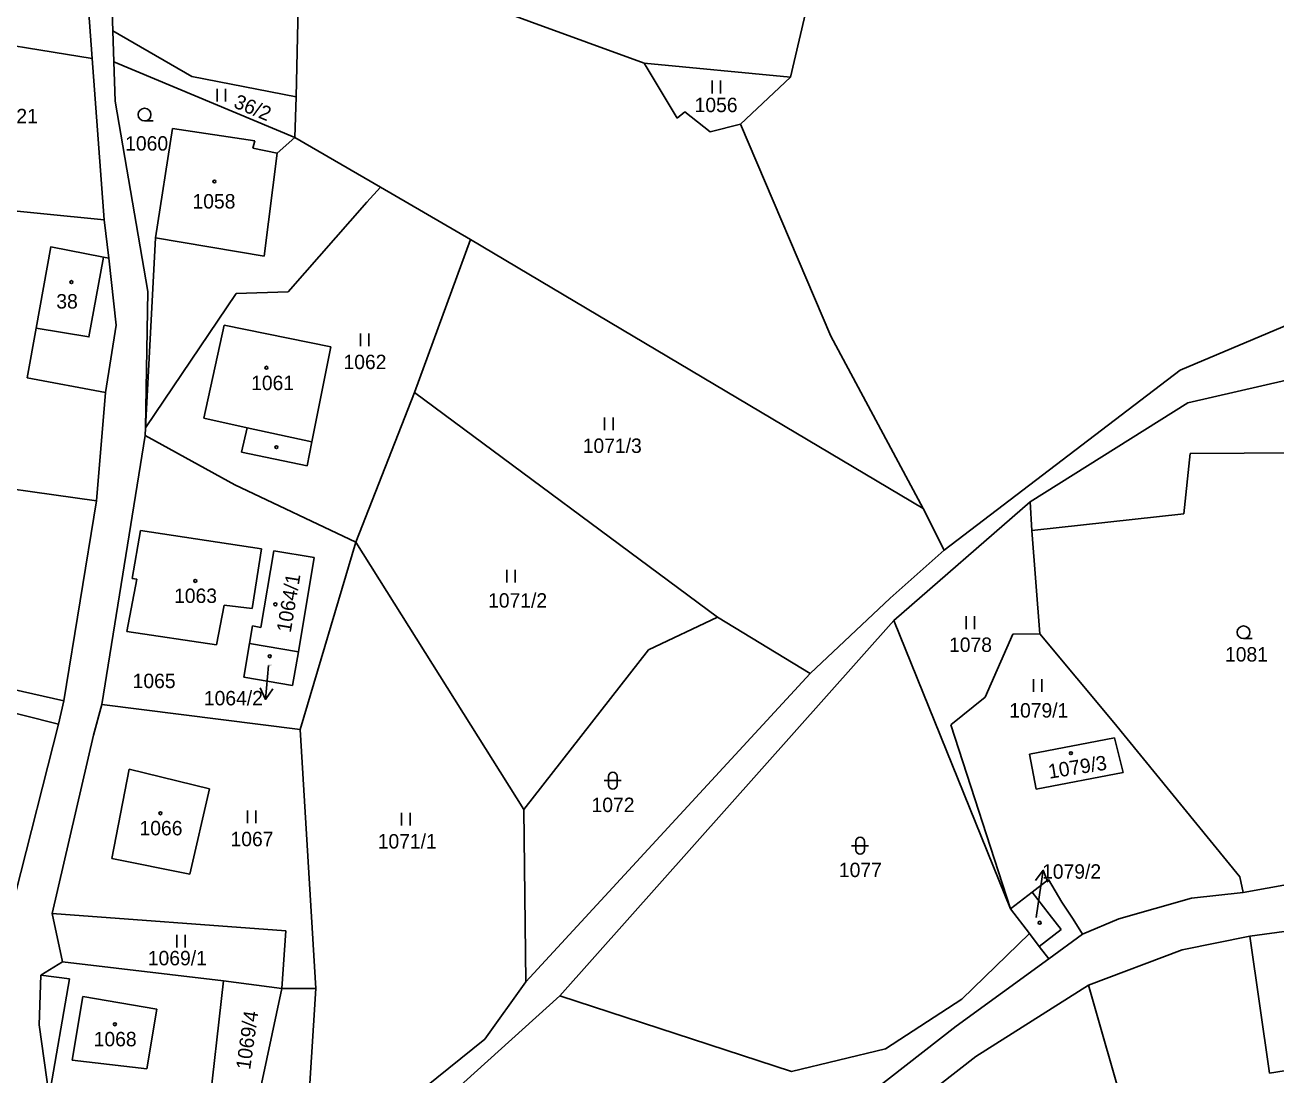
# Model space of a CAD drawing. Extents: x -670359 to -668019, y -978807 to -976674.
# Drawn here: x -670130.3 to -669982.9, y -977711.4 to -977587.7 of the extents above; entities that cross this region are included whole.
import ezdxf

# ---------------------------------------------------------------- set-up
doc = ezdxf.new("R2010")
doc.units = 0
for name, color, linetype in [('Hranice parcel', 7, 'Continuous'), ('Parcelní čísla', 7, 'Continuous'), ('Vnitřní kresba', 7, 'Continuous'), ('Značky budov', 7, 'Continuous'), ('Značky kultur', 7, 'Continuous')]:
    doc.layers.add(name, color=color, linetype=linetype)

msp = doc.modelspace()

# ---------------------------------------------------------------- linework, layer by layer
at = {"layer": 'Hranice parcel'}
msp.add_line((-670106.89, -977700.29), (-670100, -977701.17), dxfattribs=at)
for points in [[(-670125.26, -977552.07), (-670122.35, -977591.65)], [(-670033.24, -977564.47), (-670040.09, -977593.86)], [(-670120.58, -977569.54), (-670119.93, -977588.41)], [(-670098.33, -977596.16), (-670097.83, -977573.12)], [(-670057.34, -977592.2), (-670077.72, -977584.8)], [(-670098.33, -977596.16), (-670110.6, -977593.79), (-670119.93, -977588.41)], [(-670119.93, -977588.41), (-670119.81, -977592.06)], [(-670139.34, -977588.92), (-670122.35, -977591.65)], [(-670120.96, -977610.65), (-670122.35, -977591.65)], [(-670119.65, -977596.66), (-670119.81, -977592.06)], [(-670119.81, -977592.06), (-670098.48, -977600.97)], [(-670040.09, -977593.86), (-670057.34, -977592.2)], [(-670053.45, -977598.69), (-670057.34, -977592.2)], [(-670040.09, -977593.86), (-670045.97, -977599.39)], [(-670115.81, -977619.08), (-670119.65, -977596.66)], [(-670098.48, -977600.97), (-670098.33, -977596.16)], [(-670052.56, -977597.95), (-670053.45, -977598.69)], [(-670049.57, -977600.29), (-670052.56, -977597.95)], [(-670114.89, -977612.77), (-670112.88, -977599.91)], [(-670112.88, -977599.91), (-670103.2, -977601.34)], [(-670045.97, -977599.39), (-670049.57, -977600.29)], [(-670045.97, -977599.39), (-670035.35, -977624.36)], [(-670103.2, -977601.34), (-670103.45, -977602.21)], [(-670100.57, -977602.79), (-670098.48, -977600.97)], [(-670098.48, -977600.97), (-670088.41, -977606.81)], [(-670103.45, -977602.21), (-670100.57, -977602.79)], [(-670089.99, -977608.59), (-670088.41, -977606.81)], [(-670077.79, -977612.97), (-670088.41, -977606.81)], [(-670135.99, -977609.18), (-670120.96, -977610.65)], [(-670099.27, -977619.12), (-670089.99, -977608.59)], [(-670120.96, -977610.65), (-670120.4, -977615.18)], [(-670116.08, -977635.17), (-670114.89, -977612.77)], [(-670077.79, -977612.97), (-670084.4, -977630.98)], [(-670024.45, -977644.67), (-670077.79, -977612.97)], [(-670128.95, -977623.4), (-670127.24, -977613.84), (-670121.02, -977615.06)], [(-670121.02, -977615.06), (-670120.4, -977615.18)], [(-670120.4, -977615.18), (-670119.52, -977623.06)], [(-669964.98, -977616.04), (-669994.19, -977628.36)], [(-670115.81, -977619.08), (-670116.08, -977635.17)], [(-670116.08, -977635.17), (-670105.41, -977619.32)], [(-670105.41, -977619.32), (-670099.27, -977619.12)], [(-670130, -977629.28), (-670128.95, -977623.4)], [(-670119.52, -977623.06), (-670120.78, -977631)], [(-670106.8, -977623.06), (-670109.2, -977634)], [(-670106.8, -977623.06), (-670094.25, -977625.63)], [(-670035.35, -977624.36), (-670024.45, -977644.67)], [(-670094.25, -977625.63), (-670096.5, -977636.81)], [(-669993.29, -977632.19), (-669970.04, -977626.86)], [(-669994.19, -977628.36), (-670022.01, -977649.57)], [(-670130, -977629.28), (-670120.78, -977631)], [(-670120.78, -977631), (-670121.83, -977643.75)], [(-670084.4, -977630.98), (-670091.3, -977648.61)], [(-670084.4, -977630.98), (-670048.71, -977657.46)], [(-670011.88, -977643.88), (-669993.29, -977632.19)], [(-670109.2, -977634), (-670104.09, -977635.16)], [(-670116.1, -977636.04), (-670116.08, -977635.17)], [(-670104.09, -977635.16), (-670104.75, -977638.03)], [(-670121.21, -977667.75), (-670116.1, -977636.04)], [(-670105.57, -977641.87), (-670114.88, -977636.72), (-670116.1, -977636.04)], [(-670096.5, -977636.81), (-670097.05, -977639.62)], [(-670097.05, -977639.62), (-670104.75, -977638.03)], [(-670139.74, -977641.23), (-670121.83, -977643.75)], [(-670091.3, -977648.61), (-670105.57, -977641.87)], [(-670121.83, -977643.75), (-670125.68, -977667.32)], [(-670027.91, -977657.85), (-670011.88, -977643.88)], [(-670022.01, -977649.57), (-670024.45, -977644.67)], [(-670011.88, -977643.88), (-670011.67, -977647.24)], [(-670117.66, -977652.9), (-670116.66, -977647.23)], [(-670116.66, -977647.23), (-670102.43, -977649.41)], [(-670011.67, -977647.24), (-670010.71, -977659.41)], [(-670091.3, -977648.61), (-670097.86, -977670.7)], [(-670091.3, -977648.61), (-670071.52, -977680.1)], [(-670102.43, -977649.41), (-670103.52, -977656.44)], [(-670102.48, -977658.66), (-670100.94, -977649.63)], [(-670100.94, -977649.63), (-670096.19, -977650.44)], [(-670096.19, -977650.44), (-670098.07, -977661.52)], [(-670022.01, -977649.57), (-670028.37, -977655.2)], [(-670118.26, -977659.13), (-670117.1, -977652.98)], [(-670117.1, -977652.98), (-670117.66, -977652.9)], [(-670106.8, -977656.02), (-670107.71, -977660.73)], [(-670103.52, -977656.44), (-670106.8, -977656.02)], [(-670028.37, -977655.2), (-670037.79, -977664.1)], [(-670067.28, -977702.04), (-670027.91, -977657.85)], [(-670056.82, -977661.32), (-670048.71, -977657.46)], [(-670048.71, -977657.46), (-670037.79, -977664.1)], [(-670027.91, -977657.85), (-670014.19, -977691.82)], [(-670107.71, -977660.73), (-670118.26, -977659.13)], [(-670103.82, -977660.54), (-670103.47, -977658.49)], [(-670103.47, -977658.49), (-670102.48, -977658.66)], [(-670010.71, -977659.41), (-670013.91, -977659.46)], [(-670010.71, -977659.41), (-670001.99, -977669.86)], [(-670104.5, -977664.53), (-670103.82, -977660.54)], [(-670103.82, -977660.54), (-670098.07, -977661.52)], [(-670013.91, -977659.46), (-670017.17, -977666.88)], [(-670098.07, -977661.52), (-670098.75, -977665.51)], [(-670071.52, -977680.1), (-670056.82, -977661.32)], [(-670143.98, -977663.19), (-670125.68, -977667.32)], [(-670098.75, -977665.51), (-670104.5, -977664.53)], [(-670037.79, -977664.1), (-670071.26, -977700.41)], [(-670125.68, -977667.32), (-670126.34, -977670.04)], [(-670122.19, -977671.34), (-670121.21, -977667.75)], [(-670097.86, -977670.7), (-670121.21, -977667.75)], [(-670017.17, -977666.88), (-670021.19, -977670.13)], [(-670126.34, -977670.04), (-670131.37, -977689.99)], [(-670097.86, -977670.7), (-670096, -977701.2)], [(-670021.19, -977670.13), (-670014.19, -977691.82)], [(-670001.99, -977669.86), (-669987.15, -977688.04)], [(-670127.06, -977692.34), (-670122.19, -977671.34)], [(-670001.92, -977671.66), (-670011.93, -977673.59)], [(-670000.91, -977675.76), (-670001.92, -977671.66)], [(-670011.93, -977673.59), (-670011.14, -977677.72)], [(-670120.05, -977685.88), (-670117.98, -977675.37)], [(-670117.98, -977675.37), (-670108.55, -977677.68)], [(-670011.14, -977677.72), (-670000.91, -977675.76)], [(-670108.55, -977677.68), (-670110.87, -977687.74)], [(-670071.26, -977700.41), (-670071.52, -977680.1)], [(-670110.87, -977687.74), (-670120.05, -977685.88)], [(-669957.62, -977684.64), (-669986.76, -977689.88)], [(-670011.62, -977689.84), (-670009.72, -977688.37)], [(-670009.72, -977688.37), (-670008.14, -977691.01)], [(-669987.15, -977688.04), (-669986.76, -977689.88)], [(-670011.62, -977689.84), (-670014.19, -977691.82)], [(-669986.76, -977689.88), (-669992.85, -977690.56)], [(-670014.19, -977691.82), (-670011.96, -977694.72)], [(-670008.14, -977691.01), (-670006.79, -977693.02)], [(-669992.85, -977690.56), (-670001.43, -977692.98)], [(-670125.86, -977698.04), (-670127.06, -977692.34)], [(-670099.55, -977694.38), (-670127.06, -977692.34)], [(-670006.79, -977693.02), (-670005.69, -977694.79)], [(-670001.43, -977692.98), (-670005.69, -977694.79)], [(-669972.97, -977693.24), (-669985.99, -977695.04)], [(-670100, -977701.17), (-670099.55, -977694.38)], [(-670019.9, -977702.45), (-670011.96, -977694.72)], [(-670011.96, -977694.72), (-670010.79, -977696.24)], [(-670005.69, -977694.79), (-670009.67, -977697.69)], [(-670010.79, -977696.24), (-670009.67, -977697.69)], [(-669985.99, -977695.04), (-669993.94, -977696.63)], [(-669985.99, -977695.04), (-669983.66, -977711.17)], [(-670020.57, -977705.64), (-670009.67, -977697.69)], [(-669993.94, -977696.63), (-670005.01, -977700.79)], [(-670128.4, -977699.61), (-670125.86, -977698.04)], [(-670125.86, -977698.04), (-670106.89, -977700.29)], [(-670128.6, -977705.45), (-670128.4, -977699.61)], [(-670106.89, -977700.29), (-670108.73, -977716.63)], [(-670071.26, -977700.41), (-670076.09, -977707.16)], [(-670124.71, -977709.64), (-670123.45, -977702.13)], [(-670123.45, -977702.13), (-670114.74, -977703.63)], [(-670100, -977701.17), (-670104.16, -977720.69)], [(-670096, -977701.2), (-670100, -977701.17)], [(-670096, -977701.2), (-670097.32, -977721.73)], [(-670097.16, -977729.02), (-670067.28, -977702.04)], [(-670067.28, -977702.04), (-670039.97, -977710.95)], [(-670005.01, -977700.79), (-670018.27, -977709.18)], [(-670005.01, -977700.79), (-669996.13, -977731.83)], [(-670114.74, -977703.63), (-670115.91, -977710.66)], [(-670028.91, -977708.31), (-670019.9, -977702.45)], [(-670128.6, -977705.45), (-670127.44, -977713.87)], [(-670020.57, -977705.64), (-670038.59, -977719.67)], [(-670076.09, -977707.16), (-670097.12, -977724.06)], [(-670039.97, -977710.95), (-670028.91, -977708.31)], [(-670018.27, -977709.18), (-670035.74, -977722.81)], [(-669983.66, -977711.17), (-669966.96, -977708.51)], [(-670115.91, -977710.66), (-670124.71, -977709.64)]]:
    msp.add_lwpolyline(points, dxfattribs=at)
at = {"layer": 'Parcelní čísla'}
for p, q in [((-670101.06, -977665.9), (-670101.92, -977667.14)), ((-670011.25, -977688.45), (-670010.32, -977687.27)), ((-670011.15, -977692.81), (-670010.91, -977691.23))]:
    msp.add_line(p, q, dxfattribs=at)
for points in [[(-670101.57, -977663.15), (-670101.92, -977667.14), (-670102.55, -977665.78)], [(-670010.91, -977691.23), (-670010.32, -977687.27), (-670009.77, -977688.67)]]:
    msp.add_lwpolyline(points, dxfattribs=at)
at = {"layer": 'Vnitřní kresba'}
for points in [[(-670100.57, -977602.79), (-670102.1, -977614.94)], [(-670102.1, -977614.94), (-670114.89, -977612.77)], [(-670121.02, -977615.06), (-670122.74, -977624.45), (-670128.95, -977623.4)], [(-670104.09, -977635.16), (-670096.5, -977636.81)], [(-669993.77, -977645.3), (-669993.01, -977638.18)], [(-669993.01, -977638.18), (-669967.58, -977638.03)], [(-670011.67, -977647.24), (-669993.77, -977645.3)], [(-670138.8, -977666.91), (-670126.34, -977670.04)], [(-670009.61, -977692.44), (-670011.62, -977689.84)], [(-670008.21, -977694.24), (-670009.61, -977692.44)], [(-670010.79, -977696.24), (-670008.21, -977694.24)], [(-670128.4, -977699.61), (-670125.04, -977700.04)], [(-670125.04, -977700.04), (-670127.44, -977713.87)]]:
    msp.add_lwpolyline(points, dxfattribs=at)
at = {"layer": 'Značky budov'}
for centre in [(-670107.96, -977606.14), (-670124.8, -977617.99), (-670101.83, -977628.08), (-670110.21, -977653.18), (-670100.78, -977655.94), (-670101.44, -977662.05), (-670007.07, -977673.47), (-670114.32, -977680.55), (-670010.74, -977693.45), (-670119.68, -977705.4)]:
    msp.add_circle(centre, 0.175, dxfattribs=at)
at = {"layer": 'Značky kultur'}
for p, q in [((-670049.33, -977594.26), (-670049.33, -977595.76)), ((-670048.33, -977595.76), (-670048.33, -977594.26)), ((-670107.64, -977595.21), (-670107.64, -977596.71)), ((-670106.64, -977596.71), (-670106.64, -977595.21)), ((-670116.19, -977599.01), (-670115.19, -977599.01)), ((-670090.75, -977624.04), (-670090.75, -977625.54)), ((-670089.75, -977625.54), (-670089.75, -977624.04)), ((-670062, -977633.92), (-670062, -977635.42)), ((-670061, -977635.42), (-670061, -977633.92)), ((-670073.52, -977651.88), (-670073.52, -977653.38)), ((-670072.52, -977653.38), (-670072.52, -977651.88)), ((-670019.42, -977657.35), (-670019.42, -977658.85)), ((-670018.42, -977658.85), (-670018.42, -977657.35)), ((-669986.73, -977659.98), (-669985.73, -977659.98)), ((-670011.47, -977664.76), (-670011.47, -977666.26)), ((-670010.47, -977666.26), (-670010.47, -977664.76)), ((-670062.03, -977676.71), (-670060.03, -977676.71)), ((-670061.53, -977676.21), (-670061.53, -977677.21)), ((-670060.53, -977676.21), (-670060.53, -977677.21)), ((-670104.06, -977680.23), (-670104.06, -977681.73)), ((-670103.06, -977681.73), (-670103.06, -977680.23)), ((-670085.91, -977680.51), (-670085.91, -977682.01)), ((-670084.91, -977682.01), (-670084.91, -977680.51)), ((-670032.89, -977684.37), (-670030.89, -977684.37)), ((-670032.39, -977683.87), (-670032.39, -977684.87)), ((-670031.39, -977683.87), (-670031.39, -977684.87)), ((-670112.39, -977694.86), (-670112.39, -977696.36)), ((-670111.39, -977696.36), (-670111.39, -977694.86))]:
    msp.add_line(p, q, dxfattribs=at)
for centre, radius in [((-670116.19, -977598.26), 0.75), ((-670107.96, -977606.14), 0.175), ((-670124.8, -977617.99), 0.175), ((-670101.83, -977628.08), 0.175), ((-670100.65, -977637.43), 0.175), ((-670110.21, -977653.18), 0.175), ((-670100.78, -977655.94), 0.175), ((-669986.73, -977659.23), 0.75), ((-670101.44, -977662.05), 0.175), ((-670007.07, -977673.47), 0.175), ((-670114.32, -977680.55), 0.175), ((-670010.74, -977693.45), 0.175), ((-670119.68, -977705.4), 0.175)]:
    msp.add_circle(centre, radius, dxfattribs=at)
for centre, start, end in [((-670061.03, -977676.21), 0, 180), ((-670061.03, -977677.21), 180, 0), ((-670031.89, -977683.87), 0, 180), ((-670031.89, -977684.87), 180, 0)]:
    msp.add_arc(centre, 0.5, start, end, dxfattribs=at)

# ---------------------------------------------------------------- texts
at = {"layer": 'Parcelní čísla'}
for s, rotation, p in [('36/2', 337.4827, (-670105.81, -977597.37)), ('1064/1', 80.3948, (-670098.97, -977659.34)), ('1079/3', 9.0395, (-670009.6, -977676.49)), ('1069/4', 81.9, (-670103.75, -977710.83))]:
    msp.add_text(s, height=1.7, rotation=rotation, dxfattribs=at).set_placement(p)
for s, height, p in [('27/21', 1.7, (-670134.45, -977599.28)), ('1056', 1.7, (-670051.39, -977597.97)), ('1060', 1.7, (-670118.47, -977602.5)), ('1058', 1.7, (-670110.54, -977609.32)), ('38', 1.7, (-670126.58, -977621.1)), ('1062', 1.7, (-670092.75, -977628.24)), ('1061', 1.7, (-670103.63, -977630.71)), ('1071/3', 1.7, (-670064.57, -977638.11)), ('1063', 1.7, (-670112.71, -977655.78)), ('1071/2', 1.7, (-670075.72, -977656.33)), ('1078', 1.7, (-670021.42, -977661.55)), ('1081', 1.7, (-669988.91, -977662.68)), ('1064/2', 0.1, (-670101.57, -977663.15)), ('1065', 1.7, (-670117.59, -977665.81)), ('1064/2', 1.7, (-670109.2, -977667.84)), ('1079/1', 1.7, (-670014.32, -977669.28)), ('1072', 1.7, (-670063.53, -977680.41)), ('1066', 1.7, (-670116.78, -977683.15)), ('1067', 1.7, (-670106.06, -977684.43)), ('1071/1', 1.7, (-670088.72, -977684.7)), ('1077', 1.7, (-670034.39, -977688.07)), ('1079/2', 1.7, (-670010.46, -977688.26)), ('1079/2', 0.1, (-670011.15, -977692.81)), ('1069/1', 1.7, (-670115.8, -977698.46)), ('1068', 1.7, (-670122.18, -977708))]:
    msp.add_text(s, height=height, dxfattribs=at).set_placement(p)

doc.saveas('drawing.dxf')
